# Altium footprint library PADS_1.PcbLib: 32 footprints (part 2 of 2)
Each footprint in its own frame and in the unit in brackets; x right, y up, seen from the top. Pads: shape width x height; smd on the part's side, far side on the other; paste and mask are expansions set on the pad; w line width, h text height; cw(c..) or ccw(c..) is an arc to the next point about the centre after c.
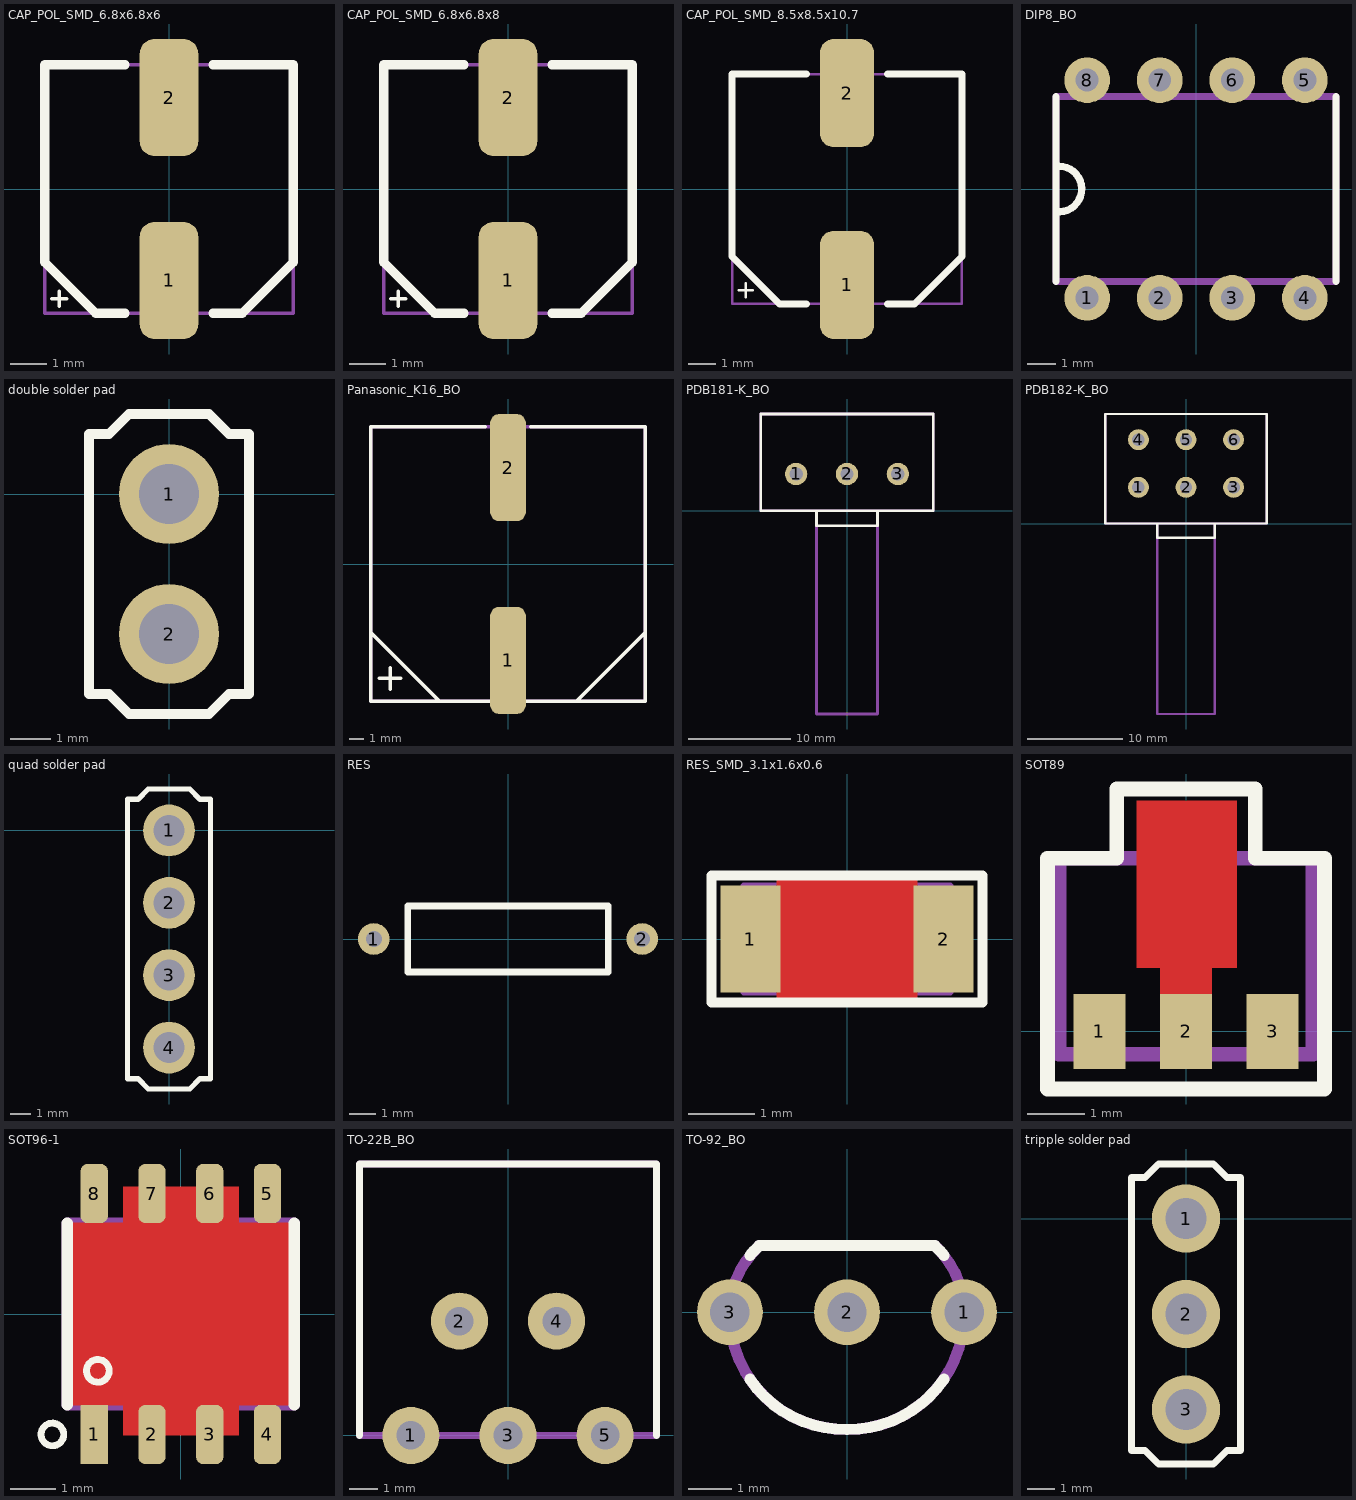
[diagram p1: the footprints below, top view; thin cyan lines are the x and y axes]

## CAP_POL_SMD_6.8x6.8x6 [mm]
height 6
pads (2):
  rrect50% 1.6x3.2 smd: 1(0,-2.5) 2(0,2.5)
Top Overlay:
  lines w0.1: -3.2,-3 -2.8,-3 ; -3,-3.2 -3,-2.8
  lines w0.254: -1.2,-3.4 -2,-3.4 -3.4,-2 -3.4,3.4 -1.2,3.4 ; 1.2,-3.4 2,-3.4 3.4,-2 3.4,3.4 1.2,3.4
Mechanical 13:
  lines w0.1: -3.4,-2 -2,-3.4 ; 2,-3.4 3.4,-2 ; -3.4,-3.4 3.4,-3.4 3.4,3.4 -3.4,3.4 -3.4,-3.4
3D body: height 4, standoff 1, extent -3.2,-3.197 3.2,3.197
3D body: height 1.5, standoff 0.3, extent -3.4,-3.4 3.4,3.4
3D body: height 1.2, standoff 0.3, extent -3.4,-3.4 3.4,3.45
3D body: height 6, standoff 1.8, extent -3.4,-3.4 3.4,3.4
3D body: height 0.3, standoff 0, extent -0.375,1.5 0.375,3.9
3D body: height 0.3, standoff 0, extent -0.375,-3.9 0.375,-1.2

## CAP_POL_SMD_6.8x6.8x8 [mm]
height 8
pads (2):
  rrect50% 1.6x3.2 smd: 1(0,-2.5) 2(0,2.5)
Top Overlay:
  lines w0.1: -3.2,-3 -2.8,-3 ; -3,-3.2 -3,-2.8
  lines w0.254: -1.2,-3.4 -2,-3.4 -3.4,-2 -3.4,3.4 -1.2,3.4 ; 1.2,-3.4 2,-3.4 3.4,-2 3.4,3.4 1.2,3.4
Mechanical 13:
  lines w0.1: -3.4,-2 -2,-3.4 ; 2,-3.4 3.4,-2 ; -3.4,-3.4 -3.4,3.4 3.4,3.4 3.4,-3.4 -3.4,-3.4
3D body: height 0.3, standoff 0, extent -0.375,-3.9 0.375,-1.2
3D body: height 0.3, standoff 0, extent -0.375,1.5 0.375,3.9
3D body: height 8, standoff 3, extent -3.4,-3.4 3.4,3.4
3D body: height 1.2, standoff 0.3, extent -3.4,-3.4 3.4,3.45
3D body: height 2.3, standoff 0.3, extent -3.4,-3.4 3.4,3.4
3D body: height 4, standoff 1, extent -3.2,-3.197 3.2,3.197

## CAP_POL_SMD_8.5x8.5x10.7 [mm]
height 10.7
pads (2):
  rrect50% 2x4 smd: 1(0,-3.55) 2(0,3.55)
Top Overlay:
  lines w0.1: -4,-3.75 -3.5,-3.75 ; -3.75,-4 -3.75,-3.5
  lines w0.254: -1.5,-4.25 -2.5,-4.25 -4.25,-2.5 -4.25,4.25 -1.5,4.25 ; 1.5,-4.25 2.5,-4.25 4.25,-2.5 4.25,4.25 1.5,4.25
Mechanical 13:
  lines w0.1: -4.25,-2.5 -2.5,-4.25 ; 2.5,-4.25 4.25,-2.5 ; -4.25,-4.25 -4.25,0 -4.25,4.25 4.25,4.25 4.25,0 4.25,-4.25 -4.25,-4.25
3D body: height 10.8, standoff 3.5, extent -4.25,-4.25 4.25,4.25
3D body: height 1.2, standoff 0.3, extent -4.3,-4.3 4.25,4.2
3D body: height 2.3, standoff 0.3, extent -4.25,-4.25 4.25,4.25
3D body: height 4, standoff 1, extent -4,-3.997 4,3.997
3D body: height 0.3, standoff 0, extent -0.5,-5 0.5,-2
3D body: height 0.3, standoff 0, extent -0.5,2 0.5,5

## DIP8_BO [mm]
pads (8):
  round 1.6 hole 0.8: 1(-3.81,-3.81) 2(-1.27,-3.81) 3(1.27,-3.81) 4(3.81,-3.81) 5(3.81,3.81) 6(1.27,3.81) 7(-1.27,3.81) 8(-3.81,3.81)
Top Overlay:
  lines w0.254: -4.9,-3.24 -4.9,3.24 ; -4.899,-0.794 ccw(c-4.8,0) -4.8,0.8 ; 4.9,-3.24 4.9,3.24
Mechanical 1:
  lines w0.254: -4.9,-3.24 -4.9,3.24 4.9,3.24 4.9,-3.24 -4.9,-3.24
3D body: height 3.2, standoff 0.51, extent -4.9,-3.24 4.9,3.24

## double solder pad [mm]
pads (2):
  round 2.5 hole 1.5: 1(0,0) 2(0,-3.5)
Top Overlay:
  lines w0.254: -2,-5 -1.5,-5 -1,-5.5 1,-5.5 1.5,-5 2,-5 2,-4.5 2,-3.125 2,0 2,1.5 1.5,1.5 1,2 -1,2 -1.5,1.5 -2,1.5 -2,0 -2,-4.5 -2,-5

## Panasonic_K16_BO [mm]
pads (2):
  rrect50% 2.5x7.5 smd: 1(0,-6.75) 2(0,6.75)
Top Overlay:
  lines w0.254: -9.6,-4.8 -4.8,-9.6 4.8,-9.6 9.6,-4.8 ; -9,-8 -7.5,-8 ; -8.25,-8.75 -8.25,-7.25 ; -1.6,-9.6 -9.6,-9.6 -9.6,9.6 -1.6,9.6 ; 1.6,-9.6 9.6,-9.6 9.6,9.6 1.6,9.6
Mechanical 13:
  lines w0.254: -9.6,-9.6 -9.6,0 -9.6,9.6 9.6,9.6 9.6,0 9.6,-9.6 -9.6,-9.6
3D body: height 0.3, standoff 0, extent -0.6,3.5 0.6,10.5
3D body: height 0.3, standoff 0, extent -0.6,-10.5 0.6,-3.5
3D body: height 4, standoff 1, extent -8.75,-8.75 8.75,8.75
3D body: height 2.3, standoff 0.3, extent -9.25,-9.25 9.25,9.25
3D body: height 1.2, standoff 0.3, extent -9.6,-9.6 9.6,9.6
3D body: height 17.2, standoff 3.5, extent -9.25,-9.25 9.25,9.25

## PDB181-K_BO [mm]
pads (3):
  round 2.2 hole 1.3: 1(-5,3.6) 2(0,3.6) 3(5,3.6)
Top Overlay:
  lines w0.254: -3,0 -3,-1.5 2.5,-1.5 3,-1.5 3,0 ; -8.5,0 -8.5,9.5 8.5,9.5 8.5,0 -8.5,0
Mechanical 13:
  lines w0.254: -3,0 -3,-20 3,-20 3,0 ; -8.5,0 -8.5,9.5 8.5,9.5 8.5,0 -8.5,0
3D body "User Library-Potentiometer.step": height 21.88, standoff -3.06, extent -8.382,-15.03 8.382,9.1

## PDB182-K_BO [mm]
pads (6):
  round 2.2 hole 1.3: 1(-5,3.8) 2(0,3.8) 3(5,3.8) 4(-5,8.8) 5(0,8.8) 6(5,8.8)
Top Overlay:
  lines w0.254: -3,0 -3,-1.5 3,-1.5 3,0 ; -8.5,0 -8.5,11.5 8.5,11.5 8.5,0 -8.5,0
Mechanical 13:
  lines w0.254: -3,0 -3,-20 3,-20 3,0 ; -8.5,0 -8.5,11.5 8.5,11.5 8.5,0 -8.5,0
3D body "User Library-PDB182-K_BOURNS.STEP": height 22.05, standoff -2.95, extent -8.5,-20 8.5,11

## quad solder pad [mm]
pads (4):
  round 2.5 hole 1.5: 1(0,0) 2(0,-3.5) 3(0,-7) 4(0,-10.5)
Top Overlay:
  lines w0.254: -2,-12 -2,-10.5 -2,0 -2,1.5 -1.5,1.5 -1,2 1,2 1.5,1.5 2,1.5 2,0 2,-3.125 2,-8.375 2,-10.5 2,-12 1.5,-12 1,-12.5 -1,-12.5 -1.5,-12 -2,-12

## RES [mm] "Raster 10mm"
pads (2):
  round 1.2 hole 0.6: 1(-5.08,0) 2(5.08,0)
Top Overlay:
  lines w0.254: -3.8,-1.25 -3.8,1.25 3.8,1.25 3.8,-1.25 -3.8,-1.25
3D body "User Library-R-Axial-0_25W-10_16.step": height 2.5, standoff -3.7, extent -5.38,-1.203 5.38,1.203

## RES_SMD_3.1x1.6x0.6 [mm] "1206"
pads (2):
  rect 0.9x1.6 smd: 1(-1.45,0) 2(1.45,0)
Top Layer:
  pour cut-out: -1.05,0.95 -1.05,-0.95 1.05,-0.95 1.05,0.95
Top Overlay:
  lines w0.15: -1.75,-0.95 2.032,-0.95 2.032,0.95 -2.032,0.95 -2.032,-0.95 1.65,-0.95
Mechanical 13:
  lines w0.1: -1.55,-0.8 -1.55,0.8 1.55,0.8 1.55,-0.8 -1.55,-0.8
3D body: height 0.6, standoff 0, extent -1.05,-0.8 1.05,0.8
3D body: height 0.6, standoff 0, extent -1.55,-0.8 -1.05,0.8
3D body: height 0.6, standoff 0, extent 1.05,-0.8 1.55,0.8

## SOT89 [mm]
pads (3):
  rect 0.9x1.3 smd: 1(-1.5,0) 2(0,0) 3(1.5,0)
Top Layer:
  region: -0.45,1.1 -0.45,0 0.45,0 0.45,1.1
  region: -0.854,1.1 0.88,1.1 0.88,4 -0.854,4
Top Overlay:
  lines w0.254: -2.4,-1 2.4,-1 2.4,3 1.2,3 1.2,4.2 -1.2,4.2 -1.2,3 -2.4,3 -2.4,-1
Mechanical 13:
  lines w0.254: -2.2,-0.4 2.2,-0.4 2.2,3 -2.2,3 -2.2,-0.4
3D body "User Library-SOT89-3.STEP": height 1.54, standoff 0, extent -2.25,-0.5 2.25,3.75

## SOT96-1 [mm]
pads (8):
  rect 0.6x1.3 smd: 1(-1.905,-2.65)
  rrect50% 0.6x1.3 smd: 2(-0.635,-2.65) 3(0.635,-2.65) 4(1.905,-2.65) 5(1.905,2.65) 6(0.635,2.65) 7(-0.635,2.65) 8(-1.905,2.65)
Top Layer:
  pour cut-out: -1.27,2.794 1.27,2.794 1.27,-2.667 -1.27,-2.667
  pour cut-out: -2.5,2.007 2.5,2.007 2.5,-2.007 -2.5,-2.007
Top Overlay:
  circle w0.15: c-1.825,-1.25 r0.25
  circle w0.15: c-2.825,-2.65 r0.25
  lines w0.254: -2.5,-2 -2.5,2 ; 2.5,-2 2.5,2
Mechanical 13:
  lines w0.254: -2.5,-2 -2.5,2 2.5,2 2.5,-2 -2.5,-2
3D body "User Library-so8.step": height 1.65, standoff -0.02, extent -2.45,-3.023 2.45,3.023

## TO-22B_BO [mm]
pads (5):
  round 2 hole 1: 1(-3.4,0) 2(-1.7,4) 3(0,0) 4(1.7,4) 5(3.4,0)
Top Overlay:
  lines w0.254: -5.2,0 -5.2,9.5 5.2,9.5 5.2,0
Mechanical 13:
  lines w0.254: -5.2,0 -5.2,9.5 5.2,9.5 5.2,0 -5.2,0
3D body "User Library-TO220-5B PCB.step": height 20.05, standoff -2.61, extent -5.08,-0.2 5.08,8.299

## TO-92_BO [mm]
pads (3):
  round 1.5 hole 0.9: 1(2.67,0) 2(0,0) 3(-2.67,0)
Top Overlay:
  lines w0.254: -2.214,1.289 cw(c-0.618,0) -1.998,1.518 ; -2.213,-1.529 ccw(c-0.049,-0.049) 0,-2.67 ccw(c0.04,-0.04) 2.21,-1.527 ; -2,1.52 2,1.52 ; 1.998,1.518 cw(c0.618,0) 2.214,1.289
Mechanical 13:
  lines w0.254: -2,1.52 2,1.52 2.069,1.451 cw(c0.618,0) 2.67,0 cw(c0.04,-0.04) 0,-2.67 cw(c-0.049,-0.049) -2.67,0 cw(c-0.618,0) -1.998,1.518

## tripple solder pad [mm]
pads (3):
  round 2.5 hole 1.5: 1(0,0) 2(0,-3.5) 3(0,-7)
Top Overlay:
  lines w0.254: -2,-8.5 -2,0 -2,1.5 -1.5,1.5 -1,2 1,2 1.5,1.5 2,1.5 2,0 2,-3.125 2,-8.5 1.5,-8.5 1,-9 -1,-9 -1.5,-8.5 -2,-8.5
